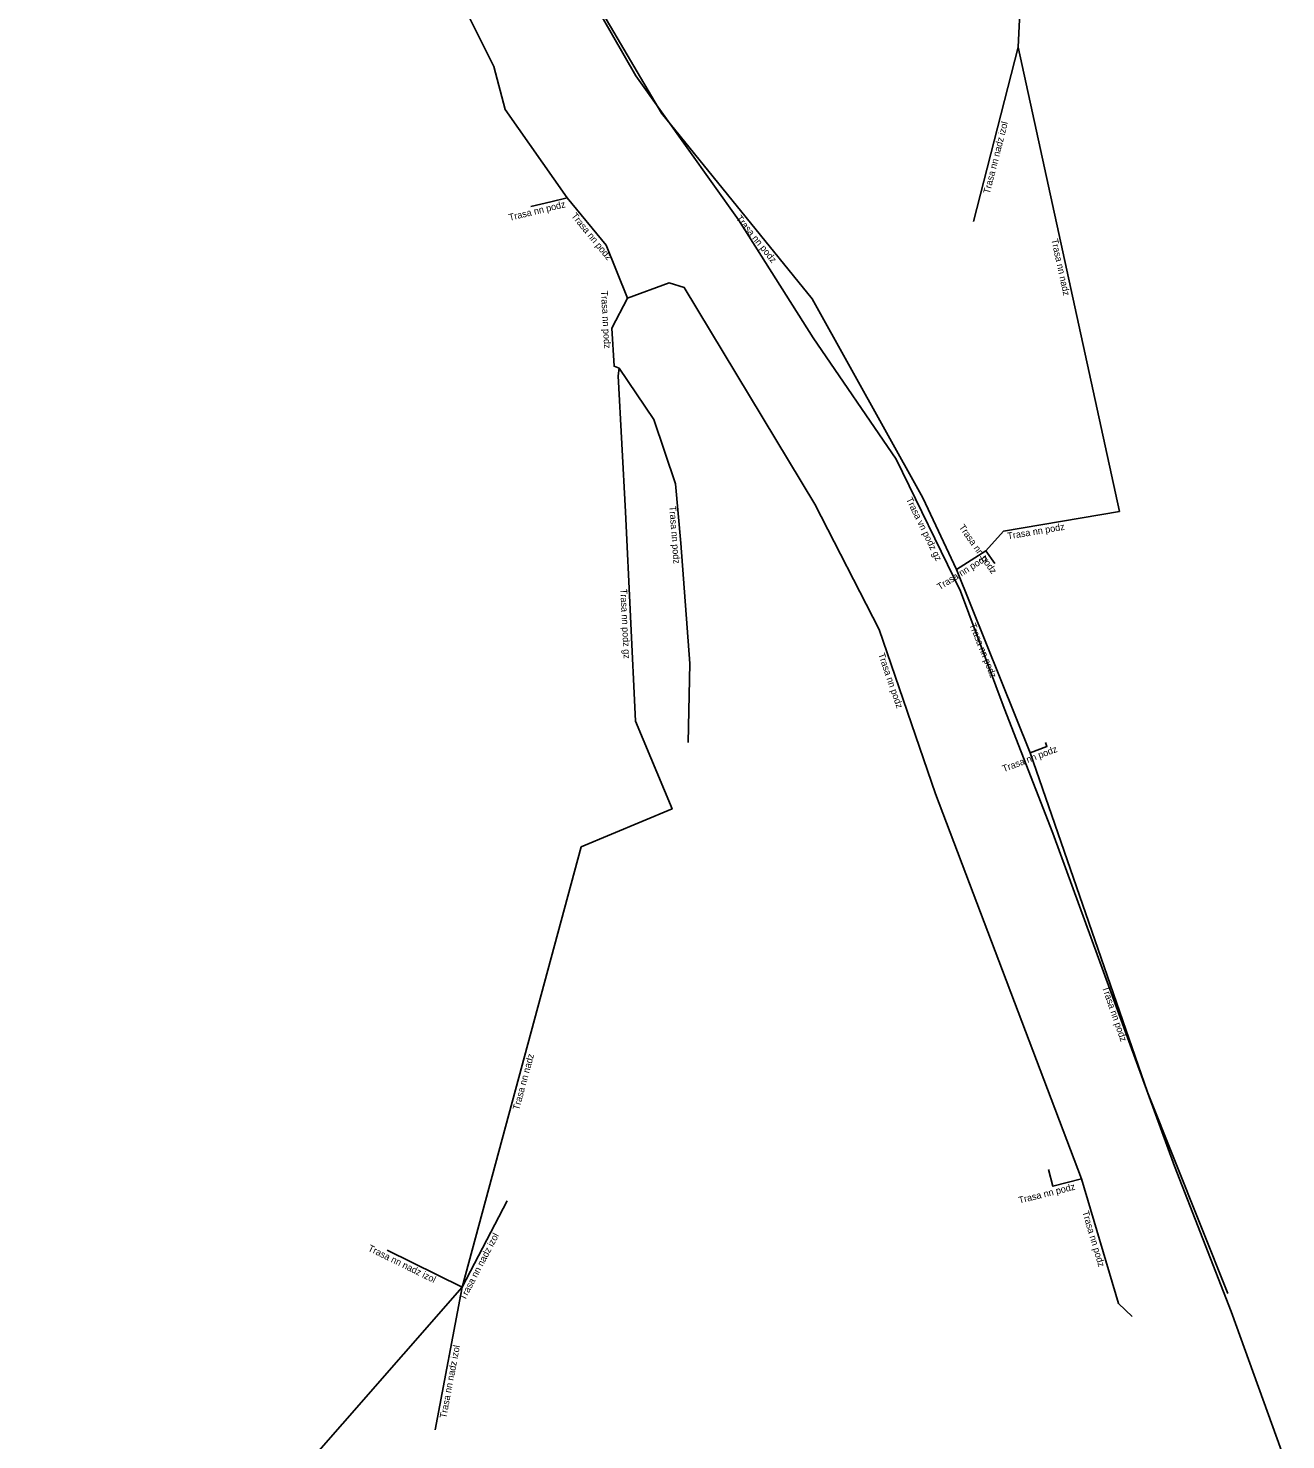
# Model space of a CAD drawing. Extents: x -748073 to -746986, y -1069233 to -1068700.
# Drawn here: x -747568.8 to -747476, y -1068988 to -1068883.9 of the extents above; entities that cross this region are included whole.
import ezdxf

# ---------------------------------------------------------------- set-up
doc = ezdxf.new("R2010")
doc.units = 0
for name, color, linetype in [('Popiskový text - Ostatní atributy Trasy', 7, 'Continuous'), ('Spojnice NN', 7, 'Continuous'), ('Spojnice VN', 7, 'Continuous')]:
    doc.layers.add(name, color=color, linetype=linetype)

msp = doc.modelspace()

# ---------------------------------------------------------------- linework, layer by layer
at = {"layer": 'Spojnice NN'}
for points in [[(-747495.77, -1068885.35), (-747494.63, -1068861.77)], [(-747543.26, -1068865.11), (-747536.89, -1068881.84), (-747534.45, -1068886.78), (-747533.6, -1068889.94), (-747529.02, -1068896.45)], [(-747500.32, -1068923.85), (-747502.81, -1068918.56), (-747510.97, -1068903.91), (-747522.08, -1068890.2), (-747529.66, -1068877.28)], [(-747495.77, -1068885.35), (-747499.06, -1068898.2)], [(-747488.29, -1068919.58), (-747495.77, -1068885.35)], [(-747529.02, -1068896.45), (-747530.23, -1068896.74), (-747531.71, -1068897.1)], [(-747524.59, -1068903.84), (-747526.15, -1068899.95), (-747529.02, -1068896.45)], [(-747491.1, -1068968.79), (-747501.86, -1068940.4), (-747506.03, -1068928.29), (-747510.77, -1068919.03), (-747520.4, -1068903.06), (-747521.5, -1068902.71), (-747524.59, -1068903.84)], [(-747525.2, -1068909.01), (-747525.57, -1068908.87), (-747525.73, -1068906.06), (-747524.59, -1068903.84)], [(-747525.2, -1068909.01), (-747525.27, -1068909.57), (-747524.74, -1068919.6), (-747523.98, -1068935.04), (-747521.29, -1068941.5), (-747527.99, -1068944.31)], [(-747525.2, -1068909.01), (-747522.63, -1068912.79), (-747521.04, -1068917.55), (-747520.64, -1068921.92), (-747519.98, -1068930.78), (-747520.11, -1068936.6)], [(-747498.15, -1068922.48), (-747496.84, -1068921.03), (-747488.29, -1068919.58)], [(-747500.32, -1068923.85), (-747498.15, -1068922.48)], [(-747498.15, -1068922.48), (-747497.5, -1068923.4)], [(-747494.89, -1068937.37), (-747500.32, -1068923.85)], [(-747494.89, -1068937.37), (-747493.65, -1068936.9), (-747493.76, -1068936.6)], [(-747480.3, -1068977.24), (-747486.23, -1068962.4), (-747494.89, -1068937.37)], [(-747536.78, -1068976.77), (-747527.99, -1068944.31)], [(-747491.1, -1068968.79), (-747493.21, -1068969.32), (-747493.54, -1068968.09)], [(-747487.35, -1068978.92), (-747488.36, -1068977.98), (-747491.1, -1068968.79)], [(-747536.78, -1068976.77), (-747533.46, -1068970.4)], [(-747536.78, -1068976.77), (-747542.31, -1068974.05)], [(-747563.09, -1069006.81), (-747536.78, -1068976.77)], [(-747536.78, -1068976.77), (-747538.76, -1068987.28)]]:
    msp.add_lwpolyline(points, dxfattribs=at)
at = {"layer": 'Spojnice VN'}
msp.add_lwpolyline([(-747568.78, -1068809.51), (-747553.42, -1068834.74), (-747546.88, -1068845.72), (-747536.13, -1068865.8), (-747529.79, -1068877.28), (-747523.97, -1068887.47), (-747516.4, -1068898.07), (-747510.89, -1068906.78), (-747504.76, -1068915.72), (-747500.03, -1068925.46), (-747496.8, -1068934.07), (-747493.21, -1068943.29), (-747484.24, -1068967.84), (-747480.06, -1068978.57), (-747476.03, -1068989.72)], dxfattribs=at)

# ---------------------------------------------------------------- texts
at = {"layer": 'Popiskový text - Ostatní atributy Trasy'}
for s, rotation, p in [('Trasa nn nadz izol', 75.6266, (-747497.87, -1068896.19)), ('Trasa nn podz', 13.6713, (-747533.27, -1068898.15)), ('Trasa nn podz', 309.3518, (-747528.76, -1068897.8)), ('Trasa nn podz', 309.0198, (-747516.61, -1068897.98)), ('Trasa nn nadz', 282.3188, (-747493.33, -1068899.53)), ('Trasa nn podz', 273.2589, (-747526.54, -1068903.31)), ('Trasa vn podz gz', 295.9024, (-747504.05, -1068918.67)), ('Trasa nn podz', 274.2681, (-747521.5, -1068919.19)), ('Trasa nn podz', 305.242, (-747500.17, -1068920.74)), ('Trasa nn podz', 9.6252, (-747496.52, -1068921.64)), ('Trasa nn podz', 32.2657, (-747501.55, -1068925.39)), ('Trasa nn podz gz', 272.818, (-747525.11, -1068925.29)), ('Trasa nn podz', 291.8817, (-747499.38, -1068927.93)), ('Trasa nn podz', 289.0008, (-747506.1, -1068930.1)), ('Trasa nn podz', 20.7583, (-747496.83, -1068938.8)), ('Trasa nn podz', 289.0848, (-747489.59, -1068954.67)), ('Trasa nn nadz', 74.8505, (-747532.58, -1068963.75)), ('Trasa nn podz', 14.1001, (-747495.67, -1068970.61)), ('Trasa nn podz', 286.602, (-747491.05, -1068971.22)), ('Trasa nn nadz izol', 62.493, (-747536.57, -1068977.78)), ('Trasa nn nadz izol', 333.834, (-747543.77, -1068974.06)), ('Trasa nn nadz izol', 79.3066, (-747537.95, -1068986.46))]:
    msp.add_text(s, height=0.5, rotation=rotation, dxfattribs=at).set_placement(p)

doc.saveas('drawing.dxf')
